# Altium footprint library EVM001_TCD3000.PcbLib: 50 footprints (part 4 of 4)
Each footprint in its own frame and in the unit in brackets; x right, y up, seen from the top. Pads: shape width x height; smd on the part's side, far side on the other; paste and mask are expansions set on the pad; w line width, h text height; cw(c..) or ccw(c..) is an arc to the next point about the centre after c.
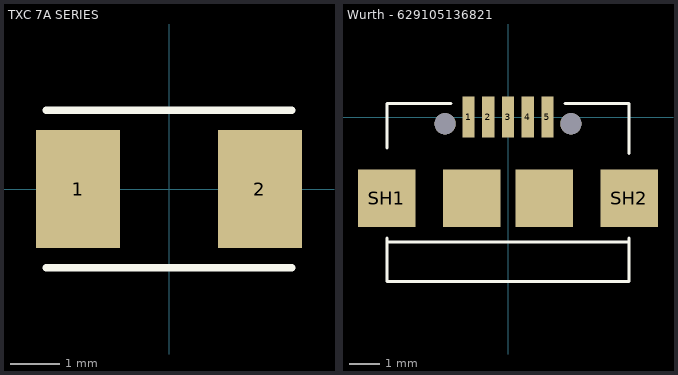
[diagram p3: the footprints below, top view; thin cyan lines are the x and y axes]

## TXC 7A SERIES [mm]
pads (2):
  rect 1.7x2.4 smd: 1(-1.85,0) 2(1.85,0)
Top Overlay:
  lines w0.15: -2.5,-1.6 2.5,-1.6 ; -2.5,1.6 2.5,1.6
3D body: height 1.2, standoff 0, extent -2.5,-1.6 2.5,1.6

## Wurth - 629105136821 [mm]
pads (11):
  rect 0.4x1.35 smd: 1(-1.3,0) 2(-0.65,0) 3(0,0) 4(0.65,0) 5(1.3,0)
  rect 1.9x1.9 smd: " "(-1.199,-2.675) " "(1.199,-2.675) SH1(-4,-2.675) SH2(4,-2.675)
  round 0.7 hole 0.7 unplated mask+0: ""(-2.075,-0.224) ""(2.075,-0.224)
Top Overlay:
  lines w0.099: -4,-4.125 4,-4.125 ; -4,-4 -4,-5.425 4,-5.425 4,-4 ; -4,-1.025 -4,0.45 -1.875,0.45 ; 1.875,0.45 4,0.45 4,-1.2
3D body: height 2.7, standoff -0.6, extent -4,-5.448 4,0.5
